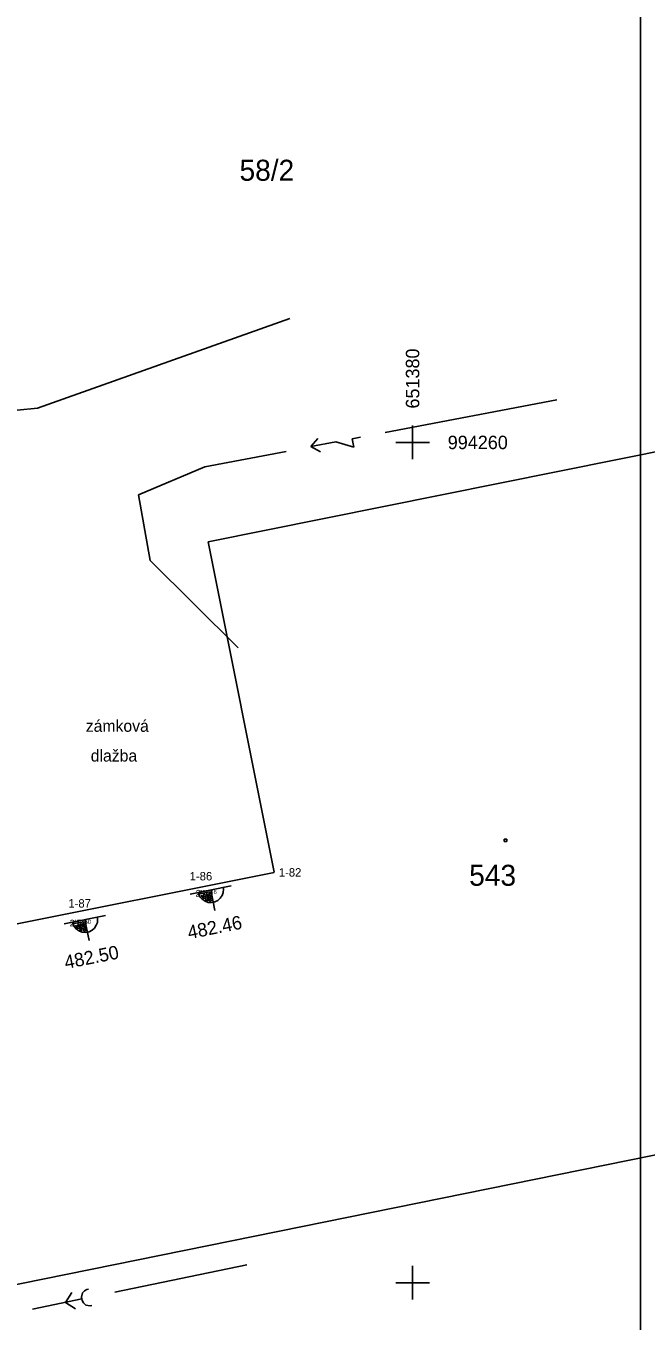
# Model space of a CAD drawing. Extents: x -651478 to -651308, y -994378 to -994071.
# Drawn here: x -651389.19 to -651374.45, y -994280.91 to -994250.09 of the extents above; entities that cross this region are included whole.
import ezdxf

# ---------------------------------------------------------------- set-up
doc = ezdxf.new("R2010")
doc.units = 0
for name, color, linetype in [('13_POPIS_POLOHOPISU', 7, 'Continuous'), ('18_TECKY_BODU', 7, 'Continuous'), ('19_CISLA_BODU', 7, 'Continuous'), ('20_REDUKOVANE_VYSKY_BODU', 7, 'Continuous'), ('30_EL-VEDENI', 7, 'Continuous'), ('34_KANAL-VEDENI', 7, 'Continuous'), ('38_VODA-VEDENI', 7, 'Continuous'), ('52_UPLNE_VYSKY_NADZEMNICH_ZNAKU', 7, 'Continuous'), ('61_UPLNE_VYSKY_BODU', 7, 'Continuous'), ('_KM', 7, 'Continuous'), ('rezy', 7, 'Continuous'), ('ROZP', 7, 'Continuous'), ('rybnik oprava', 7, 'Continuous')]:
    doc.layers.add(name, color=color, linetype=linetype)

# ---------------------------------------------------------------- blocks, each defined once
blk = doc.blocks.new('POINT_DISPLAY')
blk.add_line((0, 0), (0, 0))
blk = doc.blocks.new('Z916')
for p, q in [((0, 0), (0, 0.5)), ((-0.5, 0), (0.5, 0)), ((-0.3, 0.04), (-0.28, 0.12)), ((-0.3, 0), (-0.3, 0.04)), ((-0.28, 0.12), (-0.24, 0.18)), ((-0.24, 0.18), (-0.18, 0.24)), ((-0.18, 0.24), (-0.12, 0.28)), ((-0.12, 0.28), (-0.04, 0.3)), ((-0.04, 0.3), (0.04, 0.3)), ((0.04, 0.3), (0.12, 0.28)), ((0.04, 0.04), (0.04, 0.26)), ((0.04, 0.26), (0.08, 0.26)), ((0.26, 0.04), (0.04, 0.04)), ((0.08, 0.26), (0.08, 0.08)), ((0.08, 0.08), (0.12, 0.08)), ((0.12, 0.28), (0.18, 0.24)), ((0.12, 0.08), (0.12, 0.24)), ((0.12, 0.24), (0.16, 0.22)), ((0.16, 0.22), (0.16, 0.08)), ((0.16, 0.08), (0.2, 0.08)), ((0.18, 0.24), (0.24, 0.18)), ((0.2, 0.08), (0.2, 0.18)), ((0.2, 0.18), (0.24, 0.12)), ((0.24, 0.18), (0.28, 0.12)), ((0.24, 0.12), (0.24, 0.08)), ((0.3, 0), (0.26, 0.04)), ((0.28, 0.12), (0.3, 0.04)), ((0.3, 0.04), (0.3, 0))]:
    blk.add_line(p, q)
blk = doc.blocks.new('Z626')
for p, q in [((-0.7, 0.2), (-0.66, 0.2)), ((-0.66, 0.2), (-0.56, 0.16)), ((-0.56, 0.16), (-0.52, 0.1)), ((-0.52, 0.1), (-0.5, 0.04)), ((-0.5, 0.04), (-0.5, -0.04)), ((-0.5, 0), (0.7, 0)), ((-0.3, 0.2), (-0.1, 0)), ((-0.1, 0), (-0.3, -0.2)), ((-0.66, -0.2), (-0.7, -0.2)), ((-0.6, -0.18), (-0.66, -0.2)), ((-0.54, -0.14), (-0.6, -0.18)), ((-0.5, -0.04), (-0.54, -0.14))]:
    blk.add_line(p, q)
blk = doc.blocks.new('Z402')
for p, q in [((-0.02, 0.02), (0.04, 0.02)), ((-0.02, -0.04), (-0.02, 0.02)), ((0.04, 0.02), (0.04, -0.04)), ((0.04, -0.04), (-0.02, -0.04))]:
    blk.add_line(p, q)
blk = doc.blocks.new('Z70')
for p, q in [((0, -0.4), (0, 0.4)), ((-0.4, 0), (0.4, 0))]:
    blk.add_line(p, q)
blk = doc.blocks.new('Z660')
for p, q in [((-0.6, 0), (-0.4, 0)), ((-0.4, 0), (-0.4, 0.2)), ((-0.4, 0.2), (0, 0)), ((0, 0), (0.6, 0)), ((0.4, 0.16), (0.6, 0)), ((0.6, 0), (0.4, -0.16))]:
    blk.add_line(p, q)

msp = doc.modelspace()

# ---------------------------------------------------------------- linework, layer by layer
at = {"layer": '30_EL-VEDENI'}
for p, q in [((-651380.649, -994259.765), (-651376.57, -994258.99)), ((-651384.94, -994260.58), (-651383.006, -994260.213)), ((-651386.52, -994261.25), (-651384.94, -994260.58)), ((-651386.24, -994262.81), (-651386.52, -994261.25)), ((-651384.15, -994264.89), (-651386.24, -994262.81))]:
    msp.add_line(p, q, dxfattribs=at)
at = {"layer": '34_KANAL-VEDENI'}
msp.add_line((-651383.94, -994279.573), (-651387.079, -994280.223), dxfattribs=at)
at = {"layer": '38_VODA-VEDENI'}
for p, q in [((-651388.919, -994259.187), (-651382.918, -994257.053)), ((-651390.168, -994259.308), (-651388.919, -994259.187))]:
    msp.add_line(p, q, dxfattribs=at)
at = {"layer": '_KM'}
for p, q in [((-651371.52, -994259.68), (-651384.86, -994262.37)), ((-651384.86, -994262.37), (-651383.29, -994270.23))]:
    msp.add_line(p, q, dxfattribs=at)
at = {"layer": 'rezy'}
msp.add_line((-651374.583, -994326.69), (-651374.583, -994242.69), dxfattribs=at)
at = {"layer": 'rybnik oprava'}
for p, q in [((-651383.287, -994270.233), (-651395.81, -994272.73)), ((-651394.16, -994281), (-651368.14, -994275.72))]:
    msp.add_line(p, q, dxfattribs=at)

# ---------------------------------------------------------------- block references
at = {"layer": '13_POPIS_POLOHOPISU', "rotation": -168.7254}
for p in [(-651384.8, -994270.65), (-651387.79, -994271.36)]:
    msp.add_blockref('Z916', p, dxfattribs=at)
at = {"layer": '18_TECKY_BODU'}
for p in [(-651383.29, -994270.22), (-651384.8, -994270.65), (-651387.79, -994271.36)]:
    msp.add_blockref('POINT_DISPLAY', p, dxfattribs=at)
at = {"layer": '30_EL-VEDENI', "rotation": -169.24400000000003}
msp.add_blockref('Z660', (-651381.828, -994259.989), dxfattribs=at)
at = {"layer": '34_KANAL-VEDENI', "rotation": -168.3052}
msp.add_blockref('Z626', (-651388.352, -994280.486), dxfattribs=at)
at = {"layer": '_KM'}
msp.add_blockref('Z402', (-651377.8, -994269.46), dxfattribs=at)
at = {"layer": 'ROZP'}
for p in [(-651380, -994260), (-651380, -994280)]:
    msp.add_blockref('Z70', p, dxfattribs=at)

# ---------------------------------------------------------------- texts
at = {"layer": '13_POPIS_POLOHOPISU'}
for s, p in [('zámková', (-651387.77, -994266.887)), ('dlažba', (-651387.652, -994267.595))]:
    msp.add_text(s, height=0.28, dxfattribs=at).set_placement(p)
at = {"layer": '19_CISLA_BODU'}
for s, p in [('1-86', (-651385.3, -994270.424)), ('1-82', (-651383.18, -994270.333)), ('1-87', (-651388.184, -994271.07))]:
    msp.add_text(s, height=0.2, dxfattribs=at).set_placement(p)
at = {"layer": '20_REDUKOVANE_VYSKY_BODU'}
for s, p in [(' 2 46', (-651385.219, -994270.81)), (' 2 50', (-651388.213, -994271.52))]:
    msp.add_text(s, height=0.16, dxfattribs=at).set_placement(p)
at = {"layer": '52_UPLNE_VYSKY_NADZEMNICH_ZNAKU'}
for s, p in [('482.46', (-651385.316, -994271.824)), ('482.50', (-651388.245, -994272.535))]:
    msp.add_text(s, height=0.32, rotation=11.2746, dxfattribs=at).set_placement(p)
at = {"layer": '61_UPLNE_VYSKY_BODU'}
for s, p in [('482 46 ', (-651385.078, -994270.75)), ('482 50 ', (-651388.068, -994271.46))]:
    msp.add_text(s, height=0.1, dxfattribs=at).set_placement(p)
at = {"layer": '_KM'}
for s, p in [('58/2', (-651384.115, -994253.773)), ('543', (-651378.655, -994270.552))]:
    msp.add_text(s, height=0.5, dxfattribs=at).set_placement(p)
at = {"layer": 'ROZP'}
msp.add_text('651380', height=0.32, rotation=90, dxfattribs=at).set_placement((-651379.84, -994259.194))
msp.add_text('994260', height=0.32, dxfattribs=at).set_placement((-651379.164, -994260.16))

doc.saveas('drawing.dxf')
